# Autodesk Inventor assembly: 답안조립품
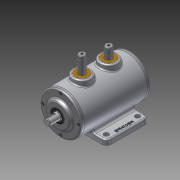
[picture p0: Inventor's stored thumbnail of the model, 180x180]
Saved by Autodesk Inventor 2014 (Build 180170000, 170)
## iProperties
Created: 2014-12
Part Number: 답안조립품
Document SubType Name: Assembly
Designer: Owner
Author: Owner
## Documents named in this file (10)
- C:\Users\Owner\Desktop\441223V1009\답안조립품.iam
- C:\Users\Owner\Desktop\441223V1009\본체.ipt
- C:\Users\Owner\Desktop\441223V1009\M4-소켓머리.ipt
- C:\Users\Owner\Desktop\441223V1009\뒷커버.ipt
- C:\Users\Owner\Desktop\441223V1009\베어링 6203.ipt
- C:\Users\Owner\Desktop\441223V1009\부시.ipt
- C:\Users\Owner\Desktop\441223V1009\슬라이더.ipt
- C:\Users\Owner\Desktop\441223V1009\앞커버.ipt
- C:\Users\Owner\Desktop\441223V1009\오일실.ipt
- C:\Users\Owner\Desktop\441223V1009\축.ipt
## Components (11 placed, 3 different names)
1. 7-베어링 6203:1
2. 8-오일실:1
3. 7-베어링 6203:2
4. 9-M4-소켓머리:2
5. 9-M4-소켓머리:3
6. 9-M4-소켓머리:4
7. 9-M4-소켓머리:5
8. 9-M4-소켓머리:1
9. 9-M4-소켓머리:6
10. 9-M4-소켓머리:7
11. 9-M4-소켓머리:8
